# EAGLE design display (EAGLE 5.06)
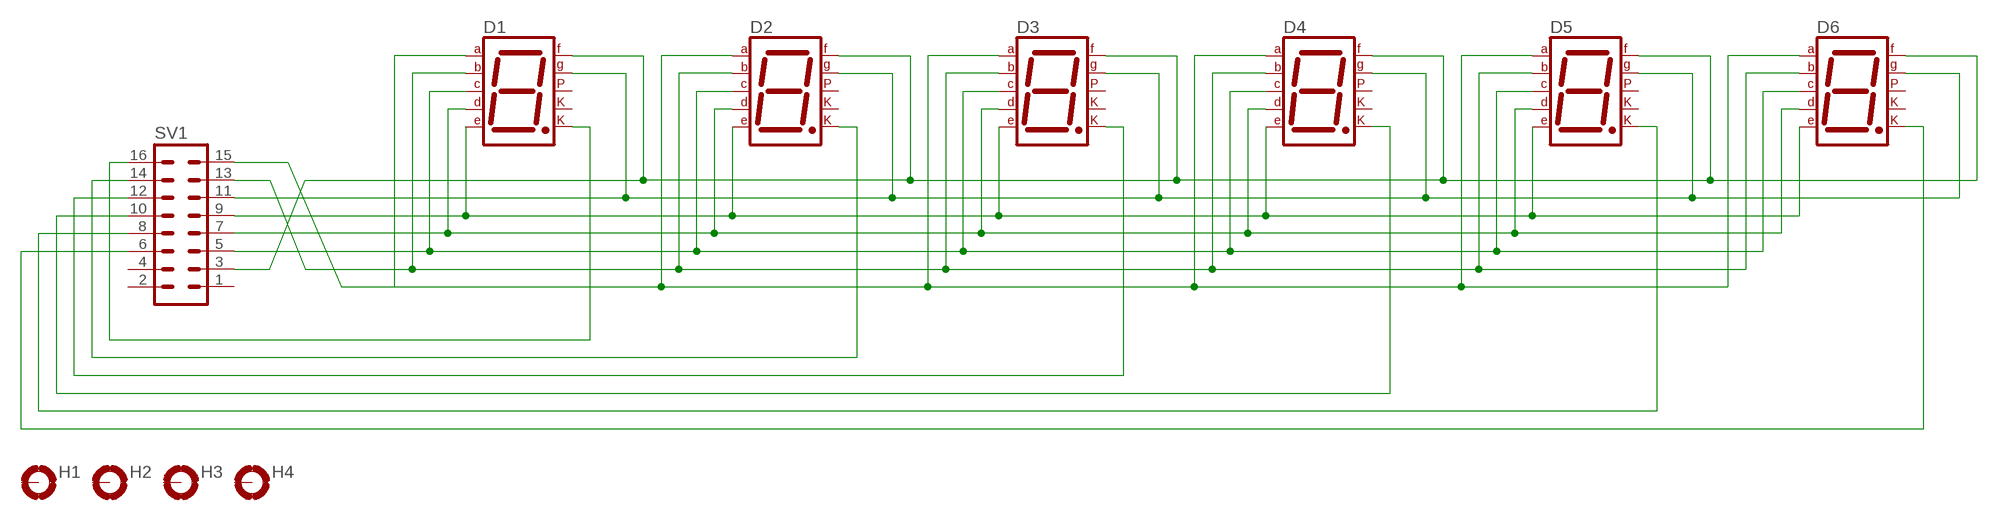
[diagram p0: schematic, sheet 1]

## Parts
D1  7SEG-CK  [7SEG-13]
D2  7SEG-CK  [7SEG-13]
D3  7SEG-CK  [7SEG-13]
D4  7SEG-CK  [7SEG-13]
D5  7SEG-CK  [7SEG-13]
D6  7SEG-CK  [7SEG-13]
H1  MOUNT-PAD-ROUND3.0  [3,0-PAD]
H2  MOUNT-PAD-ROUND3.0  [3,0-PAD]
H3  MOUNT-PAD-ROUND3.0  [3,0-PAD]
H4  MOUNT-PAD-ROUND3.0  [3,0-PAD]
SV1  MA08-2  [MA08-2]

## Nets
N$1: D1.8(CK2) SV1.16
N$2: D1.1(E) D2.1(E) D3.1(E) D4.1(E) D5.1(E) D6.1(E) SV1.9
N$3: D2.8(CK2) SV1.14
N$4: D5.8(CK2) SV1.8
N$6: D4.8(CK2) SV1.10
N$8: D3.8(CK2) SV1.12
N$9: D1.7(A) D2.7(A) D3.7(A) D4.7(A) D5.7(A) D6.7(A) SV1.15
N$10: D1.6(B) D2.6(B) D3.6(B) D4.6(B) D5.6(B) D6.6(B) SV1.13
N$11: D1.2(D) D2.2(D) D3.2(D) D4.2(D) D5.2(D) D6.2(D) SV1.7
N$12: D1.9(F) D2.9(F) D3.9(F) D4.9(F) D5.9(F) D6.9(F) SV1.3
N$13: D1.10(G) D2.10(G) D3.10(G) D4.10(G) D5.10(G) D6.10(G) SV1.11
N$14: D1.4(C) D2.4(C) D3.4(C) D4.4(C) D5.4(C) D6.4(C) SV1.5
N$16: D6.8(CK2) SV1.6
Unconnected: D1.3(CK1) D1.5(DP) D2.3(CK1) D2.5(DP) D3.3(CK1) D3.5(DP) D4.3(CK1) D4.5(DP) D5.3(CK1) D5.5(DP) D6.3(CK1) D6.5(DP) H1.B3,0(MOUNT) H2.B3,0(MOUNT) H3.B3,0(MOUNT) H4.B3,0(MOUNT) SV1.1 SV1.2 SV1.4

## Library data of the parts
D1-D6 = special:7SEG-CK: 7-segment DISPLAY single cathode, 13 mm
H1-H4 = holes:MOUNT-PAD-ROUND: MOUNTING PAD, round
SV1 = con-lstb:MA08-2: PIN HEADER

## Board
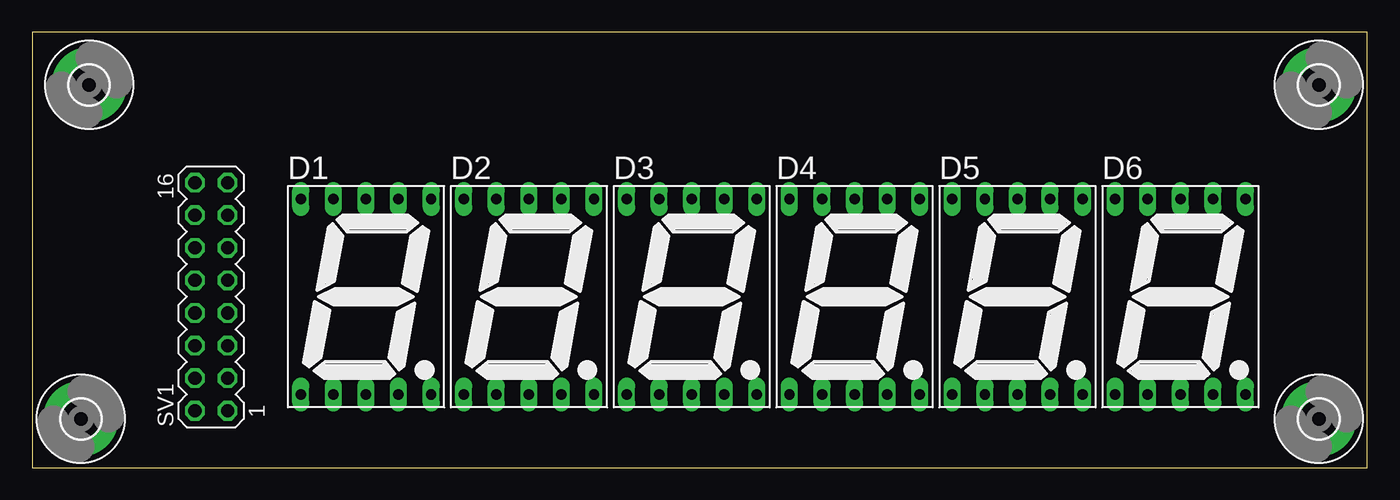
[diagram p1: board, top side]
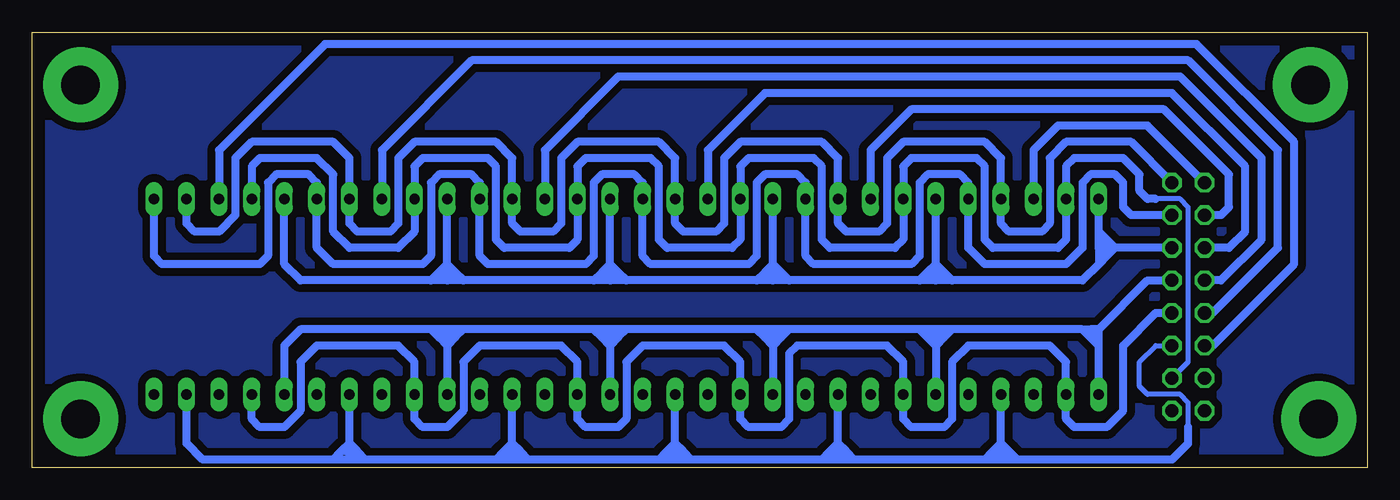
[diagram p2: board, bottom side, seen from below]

Size 104.12 x 33.96 mm. Coordinates in mm from the lower left corner, seen from the top.
Outline: 0,0 104.12,0 104.12,33.96 0,33.96 0,0
Copper layers (1*16): Top 0.035mm / dielectric 1.5mm / Bottom 0.035mm
Design rules "default": minimum track width 10mil, minimum drill 24mil, track to track 8mil, track to pad 8mil, pad to pad 8mil, via to via 8mil, smd to smd 8mil, copper to edge 40mil, drill to drill 8mil, minimum pad ring 10mil, minimum via ring 8mil, stop-mask expansion 4mil, vias tented up to drill 0mil, thermal gap 10mil

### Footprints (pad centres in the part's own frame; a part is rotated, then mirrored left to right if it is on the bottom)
7SEG-13 = drill 0.813 long: 1 -5.08,-7.62; 2 -2.54,-7.62; 3 0,-7.62; 4 2.54,-7.62; 5 5.08,-7.62; 6 5.08,7.62; 7 2.54,7.62; 8 0,7.62; 9 -2.54,7.62; 10 -5.08,7.62
3,0-PAD = drill 3 pad 5.842 round: B3,0 0,0
MA08-2 = drill 1.016 octagon: 1 -8.89,-1.27; 2 -8.89,1.27; 3 -6.35,-1.27; 4 -6.35,1.27; 5 -3.81,-1.27; 6 -3.81,1.27; 7 -1.27,-1.27; 8 -1.27,1.27; 9 1.27,-1.27; 10 1.27,1.27; 11 3.81,-1.27; 12 3.81,1.27; 13 6.35,-1.27; 14 6.35,1.27; 15 8.89,-1.27; 16 8.89,1.27

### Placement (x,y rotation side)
D1  26.04,13.34 0 top
D2  38.73,13.34 0 top
D3  51.44,13.34 0 top
D4  64.14,13.34 0 top
D5  76.83,13.34 0 top
D6  89.53,13.34 0 top
H1  3.81,3.81 0 top
H2  4.45,29.84 0 top
H3  100.33,3.81 0 top
H4  100.33,29.84 0 top
SV1  13.97,13.34 90 top

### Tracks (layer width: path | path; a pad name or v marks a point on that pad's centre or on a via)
N$1
  Bottom 0.61: SV1.16 17.14,26.67 24.13,26.67 26.04,24.77 D1.8
N$2
  Bottom 0.61: SV1.9 17.14,14.61 20.95,10.79 | 20.95,10.79 21.59,10.79 | 22.23,10.79 21.59,10.79 | 22.23,10.79 32.38,10.79 | 32.38,10.79 33.66,10.79 | 33.66,10.79 34.92,10.79 | 34.92,10.79 45.09,10.79 | 45.09,10.79 46.35,10.79 | 46.35,10.79 47.62,10.79 | 47.62,10.79 57.78,10.79 | 57.78,10.79 59.05,10.79 | 59.05,10.79 60.33,10.79 | 60.33,10.79 70.48,10.79 | 70.48,10.79 71.12,10.16 | 20.95,10.16 20.95,10.79 | D1.1 20.95,9.53 | 33.66,10.79 33.66,9.53 | 33.66,9.53 D2.1 | 46.35,10.79 46.35,9.53 | 46.35,9.53 D3.1 | 59.05,10.79 59.05,9.53 | 59.05,9.53 D4.1 | 32.38,10.79 33.02,10.16 | 33.02,10.16 33.66,9.53 | 33.66,9.53 34.29,10.16 | 34.92,10.79 34.29,10.16 | 45.09,10.79 45.72,10.16 | 45.72,10.16 46.35,9.53 | 46.35,9.53 46.99,10.16 | 47.62,10.79 46.99,10.16 | 57.78,10.79 58.42,10.16 | 58.42,10.16 59.05,9.53 | 59.05,9.53 59.69,10.16 | 60.33,10.79 59.69,10.16 | 20.95,9.53 22.23,10.79 | 20.95,9.53 20.95,10.16 | 20.95,10.16 21.59,10.79 | 59.05,10.79 58.42,10.16 | 59.05,10.79 59.69,10.16 | 46.35,10.79 45.72,10.16 | 46.35,10.79 46.99,10.16 | 33.66,10.79 33.02,10.16 | 33.66,10.79 34.29,10.16 | 71.75,9.53 D5.1 | 72.39,10.16 71.75,9.53 | 73.03,10.79 72.39,10.16 | 73.03,10.79 83.19,10.79 84.45,9.53 D6.1 | 70.48,10.79 71.75,10.79 | 71.75,10.79 73.03,10.79 | 71.75,10.79 72.39,10.16 | 71.12,10.16 71.75,10.79 | 71.12,10.16 71.75,9.53 | 71.75,10.79 71.75,9.53
N$3
  Bottom 0.61: SV1.14 11.43,19.68 10.79,20.32 10.79,22.86 15.88,27.94 35.56,27.94 38.73,24.77 D2.8
N$4
  Bottom 0.61: SV1.8 12.06,12.06 6.99,17.14 6.99,24.77 13.97,31.75 69.85,31.75 76.83,24.77 D5.8
N$6
  Bottom 0.61: D4.8 64.14,24.77 58.42,30.48 14.61,30.48 8.26,24.13 8.26,17.78 11.43,14.61 SV1.10
N$8
  Bottom 0.61: SV1.12 10.79,17.14 9.53,18.41 9.53,23.5 15.24,29.21 46.99,29.21 51.44,24.77 D3.8
N$9
  Bottom 0.61: SV1.15 18.41,25.4 23.5,25.4 24.77,24.13 24.77,19.05 25.4,18.41 27.94,18.41 28.57,19.05 D1.7 28.57,24.13 29.84,25.4 36.2,25.4 37.47,24.13 37.47,19.05 38.1,18.41 40.64,18.41 41.27,19.05 D2.7 41.27,24.13 42.55,25.4 48.9,25.4 50.16,24.13 50.16,19.05 50.8,18.41 53.34,18.41 53.98,19.05 D3.7 53.98,24.13 55.24,25.4 61.59,25.4 62.87,24.13 62.87,19.05 63.5,18.41 66.04,18.41 66.67,19.05 D4.7 66.67,24.13 67.94,25.4 74.3,25.4 75.56,24.13 75.56,19.05 76.2,18.41 78.74,18.41 79.38,19.05 D5.7 79.38,24.13 80.64,25.4 87,25.4 88.27,24.13 88.27,19.68 89.53,18.41 91.44,18.41 92.08,19.05 D6.7
N$10
  Bottom 0.61: SV1.13 18.41,19.68 19.05,20.32 19.05,22.23 19.68,22.86 21.59,22.86 22.23,22.23 22.23,17.14 23.5,15.88 29.84,15.88 31.11,17.14 D1.6 31.11,22.23 31.75,22.86 34.29,22.86 34.92,22.23 34.92,16.51 35.56,15.88 43.18,15.88 43.81,16.51 D2.6 43.81,22.23 44.45,22.86 46.99,22.86 47.62,22.23 47.62,16.51 48.26,15.88 55.88,15.88 56.52,16.51 D3.6 56.52,22.23 57.15,22.86 59.69,22.86 60.33,22.23 60.33,16.51 60.96,15.88 68.58,15.88 69.22,16.51 D4.6 69.22,22.23 69.85,22.86 72.39,22.86 73.03,22.23 73.03,16.51 73.66,15.88 80.64,15.88 81.92,17.14 D5.6 81.92,22.23 82.55,22.86 85.09,22.86 85.72,22.23 85.72,16.51 86.36,15.88 93.98,15.88 94.61,16.51 D6.6
N$11
  Bottom 0.61: SV1.7 16.51,12.06 19.05,9.53 19.05,4.45 20.32,3.17 22.86,3.17 23.5,3.81 D1.2 23.5,8.26 24.77,9.53 31.11,9.53 32.38,8.26 32.38,3.81 33.02,3.17 35.56,3.17 36.2,3.81 D2.2 36.2,8.26 37.47,9.53 44.45,9.53 45.09,8.89 45.09,3.81 45.72,3.17 48.26,3.17 48.9,3.81 D3.2 48.9,8.26 50.16,9.53 56.52,9.53 57.78,8.26 57.78,3.81 58.42,3.17 60.96,3.17 61.59,3.81 D4.2 61.59,8.26 62.87,9.53 69.22,9.53 70.48,8.26 70.48,4.45 71.75,3.17 73.66,3.17 74.3,3.81 D5.2 74.3,8.26 75.56,9.53 81.92,9.53 83.19,8.26 83.19,4.45 84.45,3.17 86.36,3.17 87,3.81 D6.2
N$12
  Bottom 0.406: SV1.3 13.97,8.26 13.97,20.32 14.61,20.95 16.51,20.95
  Bottom 0.61: 16.51,20.95 17.14,20.95 17.78,21.59 17.78,22.86 19.05,24.13 22.86,24.13 23.5,23.5 D1.9 23.5,17.78 24.13,17.14 29.21,17.14 29.84,17.78 29.84,23.5 30.48,24.13 35.56,24.13 36.2,23.5 D2.9 36.2,17.78 36.83,17.14 41.91,17.14 42.55,17.78 42.55,23.5 43.18,24.13 48.26,24.13 48.9,23.5 D3.9 48.9,17.78 49.53,17.14 54.61,17.14 55.24,17.78 55.24,23.5 55.88,24.13 60.96,24.13 61.59,23.5 D4.9 61.59,17.78 62.23,17.14 67.31,17.14 67.94,17.78 67.94,23.5 68.58,24.13 73.66,24.13 74.3,23.5 D5.9 74.3,18.41 75.56,17.14 79.38,17.14 80.64,18.41 80.64,22.86 81.92,24.13 86.36,24.13 87,23.5 D6.9
N$13
  Bottom 0.61: SV1.11 19.68,17.14 | 19.68,17.14 20.95,17.14 | 20.95,17.14 20.95,15.88 | 20.95,17.14 20.95,18.41 | 20.95,18.41 D1.10 | 20.95,15.88 22.23,14.61 32.38,14.61 | 32.38,14.61 33.66,14.61 | 33.66,14.61 34.92,14.61 | 34.92,14.61 45.09,14.61 | 45.09,14.61 46.35,14.61 | 46.35,14.61 47.62,14.61 | 47.62,14.61 57.78,14.61 | 57.78,14.61 59.05,14.61 | 59.05,14.61 60.33,14.61 | 60.33,14.61 70.48,14.61 | 46.35,14.61 46.35,15.88 | 46.35,15.88 D3.10 | 33.66,14.61 33.66,15.88 | 33.66,15.88 D2.10 | 59.05,14.61 59.05,15.88 | 59.05,15.88 D4.10 | 33.66,15.88 34.29,15.24 | 34.92,14.61 34.29,15.24 | 32.38,14.61 33.02,15.24 | 33.02,15.24 33.66,15.88 | 45.09,14.61 45.72,15.24 | 45.72,15.24 46.35,15.88 | 46.35,15.88 46.99,15.24 | 47.62,14.61 46.99,15.24 | 57.78,14.61 58.42,15.24 | 58.42,15.24 59.05,15.88 | 59.05,15.88 59.69,15.24 | 60.33,14.61 59.69,15.24 | 70.48,14.61 71.12,15.24 | 71.12,15.24 71.75,15.88 | 20.32,16.51 20.95,15.88 | 19.68,17.14 20.32,16.51 | 19.68,17.14 20.32,17.78 | 20.32,17.78 20.95,18.41 | 20.32,16.51 20.32,17.78 | 33.66,14.61 33.02,15.24 | 33.66,14.61 34.29,15.24 | 20.95,17.14 20.32,17.78 | 20.95,17.14 20.32,16.51 | 46.35,14.61 45.72,15.24 | 46.35,14.61 46.99,15.24 | 59.05,14.61 58.42,15.24 | 59.05,14.61 59.69,15.24 | 71.75,15.88 D5.10 | 71.75,15.88 72.39,15.24 | 73.03,14.61 72.39,15.24 | 73.03,14.61 83.19,14.61 84.45,15.88 D6.10 | 70.48,14.61 71.75,14.61 | 71.75,14.61 73.03,14.61 | 71.75,14.61 71.75,15.88 | 71.12,15.24 71.75,14.61 | 71.75,14.61 72.39,15.24
N$14
  Bottom 0.406: SV1.5 16.51,9.53 17.78,8.26 17.78,6.35 17.14,5.71 14.61,5.71 13.97,5.08 13.97,3.17
  Bottom 0.61: 27.3,0.64 15.24,0.64 13.97,1.91 13.97,3.17 | 27.3,0.64 28.57,0.64 | 28.57,0.64 28.57,1.91 | 28.57,1.91 D1.4 | 40.01,0.64 41.27,0.64 | 52.7,0.64 53.98,0.64 | 53.98,0.64 55.24,0.64 | 55.24,0.64 65.41,0.64 | 65.41,0.64 66.67,0.64 | 66.67,0.64 67.94,0.64 | 67.94,0.64 78.11,0.64 | 78.11,0.64 78.74,1.27 | 78.74,1.27 79.38,1.91 | 66.67,0.64 66.67,1.91 | 66.67,1.91 D4.4 | 41.27,0.64 41.27,1.91 | 41.27,1.91 D2.4 | 53.98,0.64 53.98,1.91 | 53.98,1.91 D3.4 | 79.38,1.91 D5.4 | 79.38,1.91 80.01,1.27 | 80.64,0.64 80.01,1.27 | 80.64,0.64 90.81,0.64 92.08,1.91 D6.4 92.08,6.35 | 78.11,0.64 79.38,0.64 | 79.38,0.64 80.64,0.64 | 78.74,1.27 79.38,1.27 | 78.74,1.27 79.38,0.64 | 79.38,0.64 79.38,1.27 | 79.38,1.27 80.01,1.27 | 65.41,0.64 66.04,1.27 | 66.04,1.27 66.67,1.91 | 66.67,1.91 67.31,1.27 | 67.94,0.64 67.31,1.27 | 66.67,0.64 67.31,1.27 | 66.67,0.64 66.04,1.27 | 41.91,0.64 42.55,0.64 | 42.55,0.64 52.7,0.64 | 52.7,0.64 53.34,1.27 | 53.34,1.27 53.98,1.91 | 53.98,1.91 54.61,1.27 | 55.24,0.64 54.61,1.27 | 53.98,0.64 53.34,1.27 | 53.98,0.64 54.61,1.27 | 28.57,0.64 29.84,0.64 | 29.84,0.64 40.01,0.64 | 40.01,0.64 40.64,1.27 | 40.64,1.27 41.27,1.91 | 41.27,1.91 41.91,1.27 | 42.55,0.64 41.91,1.27 | 41.91,0.64 41.91,1.27 | 41.27,0.64 41.91,0.64 | 41.27,0.64 40.64,1.27 | 27.3,0.64 27.94,1.27 | 27.94,1.27 28.57,1.91 | 28.57,1.91 29.21,1.27 | 29.84,0.64 29.21,1.27 | 28.57,0.64 29.21,1.27 | 28.57,0.64 27.94,1.27
N$16
  Bottom 0.61: D6.8 89.53,24.77 81.28,33.02 13.34,33.02 5.71,25.4 5.71,15.88 12.06,9.53 SV1.6
N$17
  pour Bottom (isolate 0.61): 0,33.66 104.14,33.66 104.14,0 0,0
